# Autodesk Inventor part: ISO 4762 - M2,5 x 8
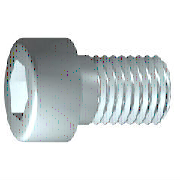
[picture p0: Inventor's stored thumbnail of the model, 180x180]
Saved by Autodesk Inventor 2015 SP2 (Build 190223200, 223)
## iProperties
IsCustomPart: 0
Created: 2012-02
Part Number: ISO 4762 - M2,5 x 8
Material: Edelstahl, 440C
Description: Innensechskantschraube
Document SubType Name: Modeling
Standard: ISO 4762
Designer: rYan
Standard Revision: 1998
Standards Organization: DIN
Language: de-DE
Size Designation: M2,5 x 8
Categories: <MemberInstance><Categories><Category DisplayName="Verbindungselemente" InternalName="e4da775c-781d-43d5-af7c-5136215cf5a6" Mnemonic="FSTN"><Category DisplayNam
Density: 7.75 g/cm^3
Mass: 0.572491 g
Surface Area: 1.353 cm^2
Volume: 0.0738699 cm^3
Appearance: Halbpoliert
Author: rYan
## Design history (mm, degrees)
sketch "Skizze1"
  geometry: L1 (-0.733, 0)-(8, 0); L2 (8, 0)-(8, 1.25); L3 (8, 1.25)-(1.125, 1.25); L4 (1.125, 1.25)-(0.849, 1.25); L5 (0.849, 1.25)-(0, 1.25); L6 (0, 1.25)-(0, 2.25); L7 (0, 2.25)-(-2.5, 2.25); L8 (-2.5, 2.25)-(-2.5, 1.155); L9 (-2.5, 1.155)-(-1.4, 1.155); L10 (-1.4, 1.155)-(-0.733, 0); L11 (-4.6, 0)-(10.1, 0) reference; L12 (0, -0.45)-(0, 2.7) reference; L13 (1.125, 1.25)-(0, 1.25)
  constraints: 22 end point, 6 parallel, 2 collinear, 2 perpendicular, 1 horizontal, 1 point on line
  dimensions: "d1" = 6.875 distance from line of L3.end L2 (= GEL); "d2" = 0.27615 distance of L4.end L3.end (computed from GAL); "d3" = 2.5 distance between parallel lines of L8 L6 (= KOH); "d4" = 1.1 distance of L8.end L9.end (= INTI); "d5" = 60 deg angle of L10 L1; "d6" = 2.5 diameter of L3 L1 (= GD); "d7" = 2.5 diameter of L5 L1 (= BDM); "d8" = 2.3094 diameter of L9 L1 (= 1.1547 x SW); "d9" = 4.5 diameter of L7 L1 (= KOD); "d26" = 8 distance between parallel lines of L12 L2 (= NLG)
revolve "Körper" sketch "Skizze1" stored, may be unused: angle "d10" = 90 deg
sketch "Skizze2"
  geometry: L1 (0, -3.15)-(0, 3.15) reference; L2 (-3.15, 0)-(3.15, 0) reference; L3 (1.155, 0)-(0.577, -1); L4 (0.577, -1)-(-0.577, -1); L5 (-0.577, -1)-(-1.155, 0); L6 (-1.155, 0)-(-0.577, 1); L7 (-0.577, 1)-(0.577, 1); L8 (0.577, 1)-(1.155, 0); 2 further points
  constraints: 12 end point, 1 coincident, 1 horizontal alignment, 1 point on line, 12 other
extrude "Loch" join sketch "Skizze2" stored distance "d11" = 10; taper "d12" = 0 deg
workplane "Work Plane1"
fillet "Fillet2" dims "d30" = 0.1 (= R)
body "Solid1"
fillet "Rundung1" dims "d17" = 0.25 (= RR)
feature "Gewinde" dims "d13" = 6.875 (= GEL), "d14" = 0
chamfer "Fase1" distance "d15" = 0.27605 (= -0.5 x SPD + 0.5 x GD); stored, may be unused: second distance "d16" = 0.27605 (= GUL), angle "d27" = 45 deg
other parameters: "GD" = 2.5 [user parameter; used in 2 equation terms], "NLG" = 8 [user parameter; used in 1 equation term], "GEL" = 6.875 [user parameter; used in 2 equation terms], "KOD" = 4.5 [user parameter; used in 1 equation term], "KOH" = 2.5 [user parameter; used in 1 equation term], "INTI" = 1.1 [user parameter; used in 1 equation term], "GAL" = 0.27605 (= 0.61345 x PTC) [user parameter; used in 1 equation term], "GUL" = 0.27605 (= 0.61345 x PTC) [user parameter; used in 1 equation term], "BDM" = 2.5 (= NND) [user parameter; used in 1 equation term], "SW" = 2 [user parameter; used in 2 equation terms], "RR" = 0.25 [user parameter; used in 1 equation term], "SPD" = 1.94789 (= NND - 1.2269 x PTC) [user parameter; used in 1 equation term], "d19" = 0, "d28" = 0, "d29" = 0, "R" = 0.1 [user parameter; used in 1 equation term], "TOA" = 30 deg [user parameter], "GD1" = 1.94789 (= THREADDIA - 1.2269 x PTC) [user parameter], "THREADDIA" = 2.5 [user parameter; used in 1 equation term], "FAWI" = 45 deg [user parameter], "TPU" = 22.22222 (computed from PTC) [user parameter], "PTC" = 0.45 [user parameter; used in 5 equation terms], "NND" = 2.5 [user parameter; used in 2 equation terms], "E0" = 2.31 (= 1.155 x SW) [user parameter]
